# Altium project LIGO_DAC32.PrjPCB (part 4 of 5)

## Sheet LD32_Power.SchDoc: Power Top
size B; SheetNumber: 3; SheetTotal: 17; PageSetup: Record=PageOptions¦CenterHorizontal=True¦CenterVertical=True¦PrintScale=1.12¦XCorrection=1.00¦YCorrection=1.00¦PrintKind=0¦BorderSize=5000000¦LeftOffset=0¦BottomOffset=0¦Orientation=2¦PaperLength=1000¦PaperWidth=1000¦Scale=100¦PaperSource=7¦PrintQuality=-4¦MediaType=1¦DitherType=10¦PaperKind=Letter¦PrintScaleMode=1
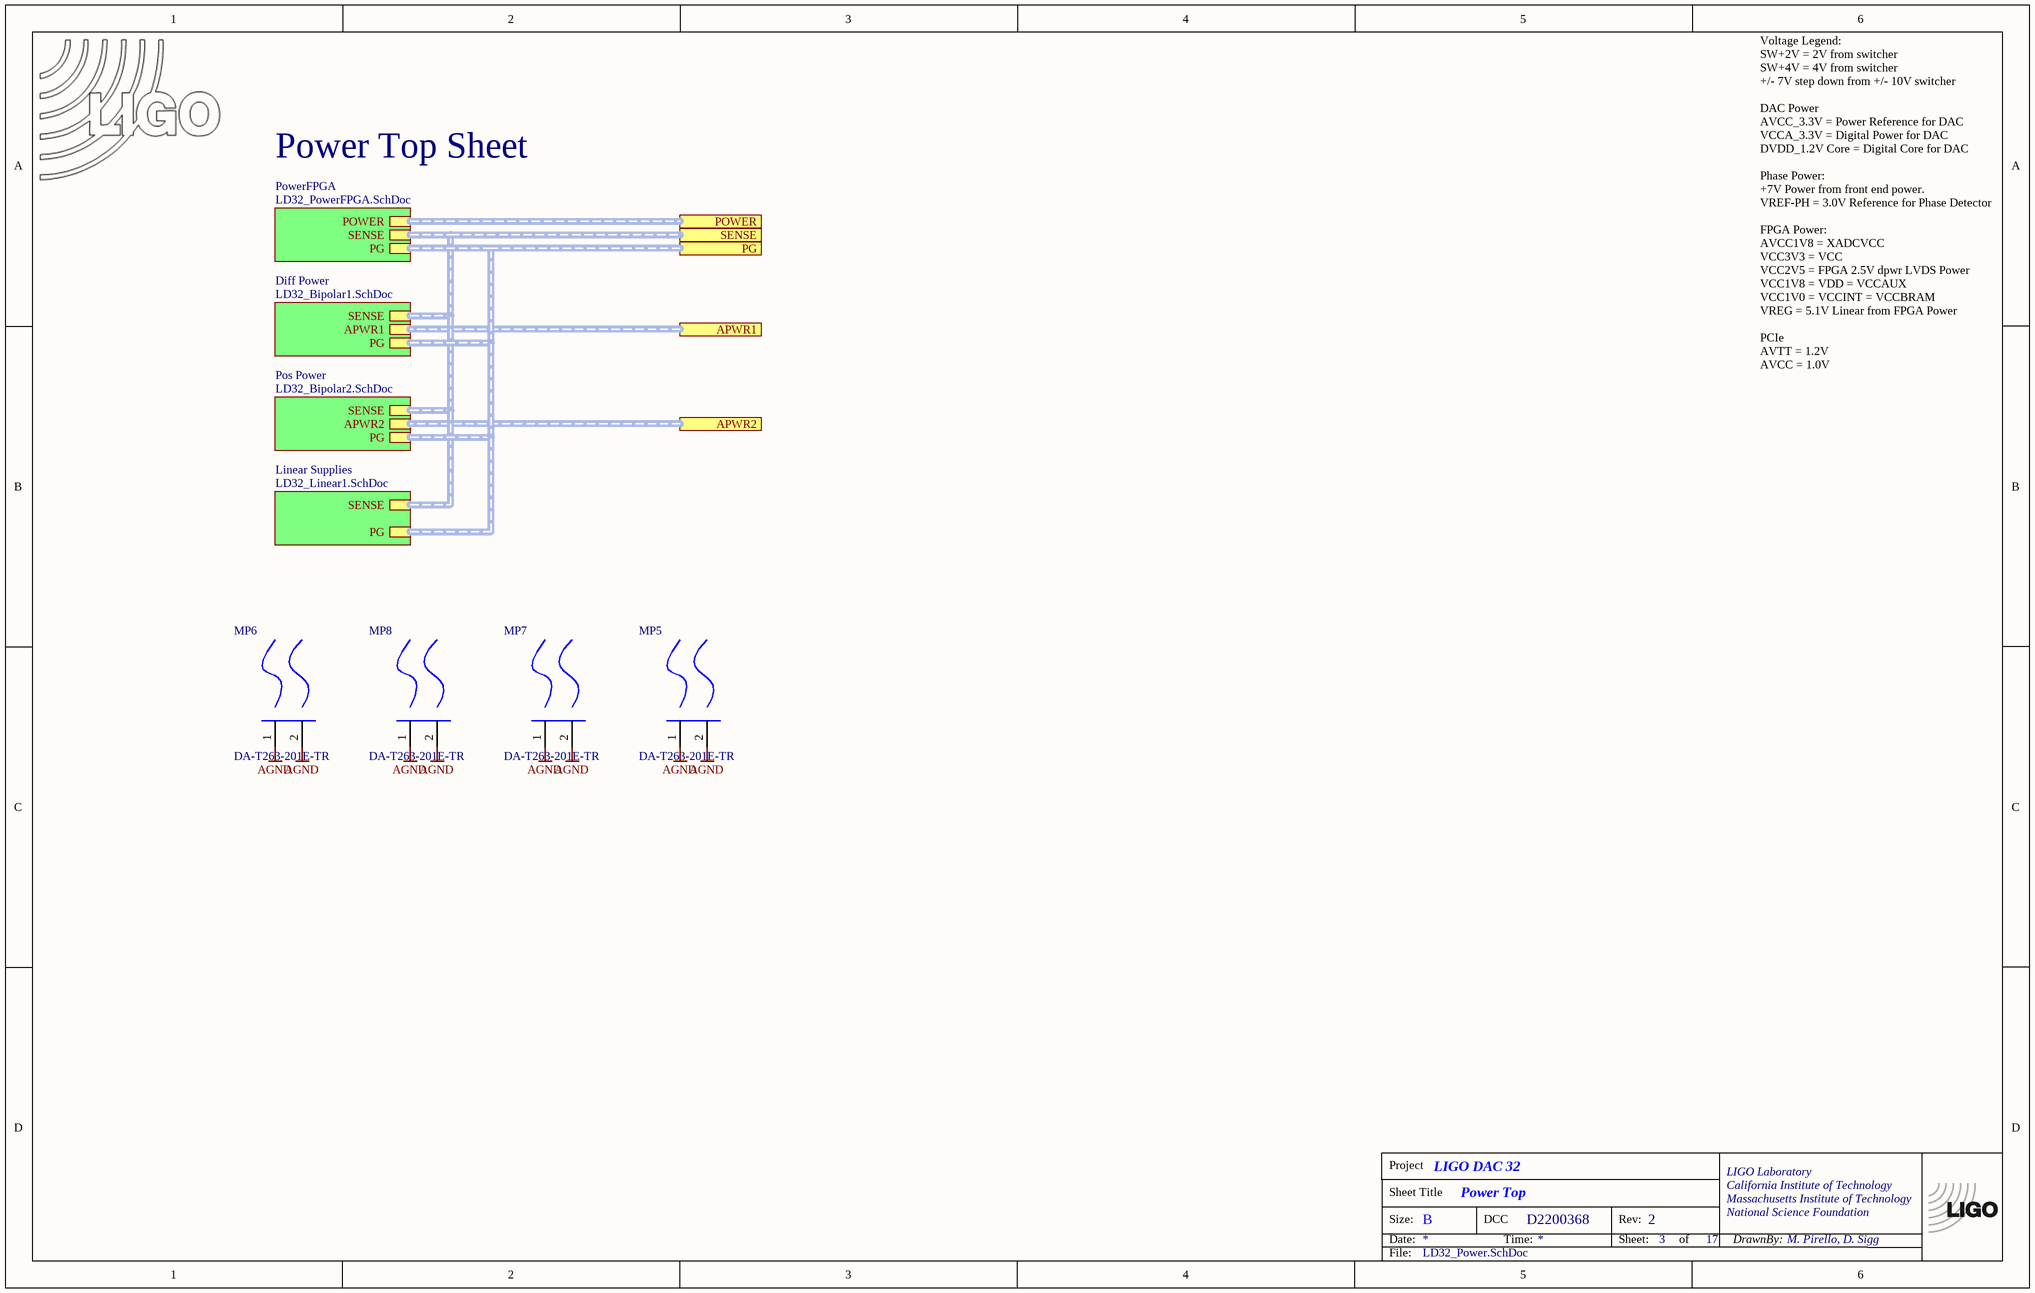
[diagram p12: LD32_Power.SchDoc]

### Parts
(Parts that share a designator on the sheet are numbered #1, #2 ... from top to bottom, then left to right.)
*?#9  TitleBlock  (value not drawn)  (graphical)
LOGO2#2  LIGO logo  [LIGO_LOGO]  (value not drawn)  (graphical)
MP5  DA-T263-201E-TR  [FP-DA-T263-201E-TR-MFG]
MP6  DA-T263-201E-TR  [FP-DA-T263-201E-TR-MFG]
MP7  DA-T263-201E-TR  [FP-DA-T263-201E-TR-MFG]
MP8  DA-T263-201E-TR  [FP-DA-T263-201E-TR-MFG]

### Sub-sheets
Diff Power = LD32_Bipolar1.SchDoc: APWR1 (harness APWR1), PG (harness APWR2), SENSE (harness SENSE)
Linear Supplies = LD32_Linear1.SchDoc: PG (harness APWR2), SENSE (harness SENSE)
Pos Power = LD32_Bipolar2.SchDoc: APWR2 (harness APWR2), PG (harness APWR2), SENSE (harness SENSE)
PowerFPGA = LD32_PowerFPGA.SchDoc: POWER (harness POWER), SENSE (harness SENSE), PG (harness APWR2)

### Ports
APWR1 (harness Inrush), APWR2 (harness Inrush), PG (harness Inrush), POWER (harness Inrush), SENSE (harness Inrush)

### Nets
AGND: MP5.1(MNT_1) MP5.2(MNT_2) MP6.1(MNT_1) MP6.2(MNT_2) MP7.1(MNT_1) MP7.2(MNT_2) MP8.1(MNT_1) MP8.2(MNT_2)

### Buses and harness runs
harness port APWR1 = sheet Diff Power/APWR1
harness port APWR2 = sheet Pos Power/APWR2
harness port PG = sheet Diff Power/PG = sheet Linear Supplies/PG = sheet Pos Power/PG = sheet PowerFPGA/PG
harness port POWER = sheet PowerFPGA/POWER
harness port SENSE = sheet Diff Power/SENSE = sheet Linear Supplies/SENSE = sheet Pos Power/SENSE = sheet PowerFPGA/SENSE

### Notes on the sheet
- Power Top Sheet
- Voltage Legend:
  SW+2V = 2V from switcher
  SW+4V = 4V from switcher
  +/- 7V step down from +/- 10V switcher
  DAC Power
  AVCC_3.3V = Power Reference for DAC
  VCCA_3.3V = Digital Power for DAC
  DVDD_1.2V Core = Digital Core for DAC
  Phase Power:
  +7V Power from front end power.
  VREF-PH = 3.0V Reference for Phase Detector
  FPGA Power:
  AVCC1V8 = XADCVCC
  VCC3V3 = VCC
  VCC2V5 = FPGA 2.5V dpwr LVDS Power
  VCC1V8 = VDD = VCCAUX
  VCC1V0 = VCCINT = VCCBRAM
  VREG = 5.1V Linear from FPGA Power
  PCIe
  AVTT = 1.2V
  AVCC = 1.0V

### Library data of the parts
LOGO2#2 = LIGO_logo
MP5-MP8 = CMP-33535-000006-1: HEATSINK FOR TO-263

## Sheet LD32_Bipolar1.SchDoc: Bipolar Analog Supply
size B; SheetNumber: 6; SheetTotal: 17
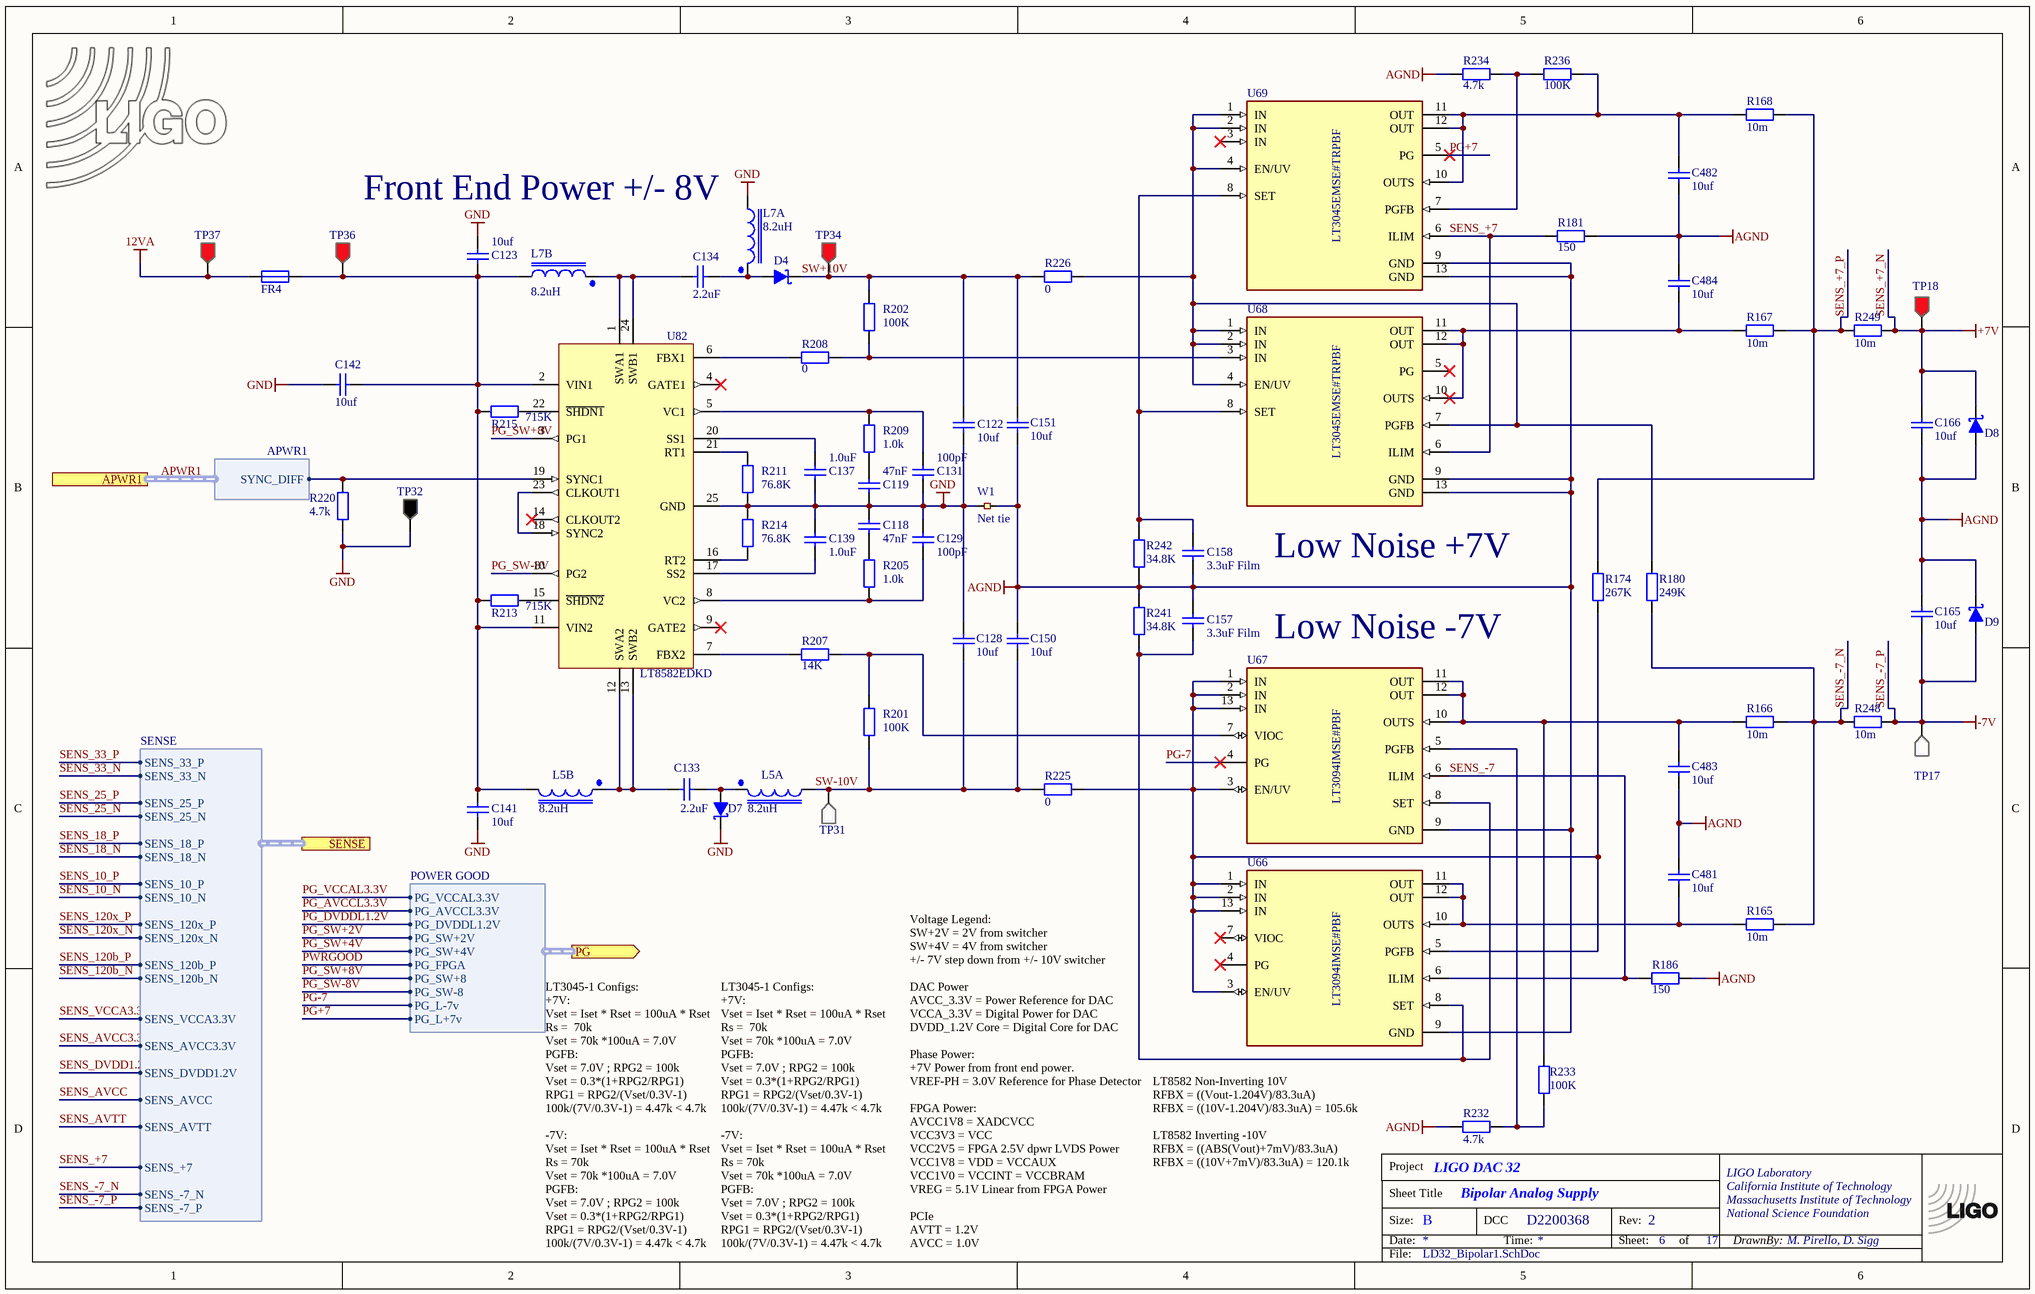
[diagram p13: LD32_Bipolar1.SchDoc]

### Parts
(Parts that share a designator on the sheet are numbered #1, #2 ... from top to bottom, then left to right.)
*?#10  TitleBlock  (value not drawn)  (graphical)
C118  47nF  [CC1005-0402]
C119  47nF  [CC1005-0402]
C122  10uF  [CC3225-1210]
C123  10uF  [CC3225-1210]
C128  10uF  [CC3225-1210]
C129  100pF  [CC1005-0402]
C131  100pF  [CC1005-0402]
C133  2.2uF  [CC3216-1206]
C134  2.2uF  [CC3216-1206]
C137  1.0uF  [CC1005-0402]
C139  1.0uF  [CC1005-0402]
C141  10uF  [CC3225-1210]
C142  10uF  [CC3225-1210]
C150  10uF  [CC3225-1210]
C151  10uF  [CC3225-1210]
C157  3.3uF Film  [CC3225-1210]
C158  3.3uF Film  [CC3225-1210]
C165  10uF  [CC3225-1210]
C166  10uF  [CC3225-1210]
C481  10uF  [CC3225-1210]
C482  10uF  [CC3225-1210]
C483  10uF  [CC3225-1210]
C484  10uF  [CC3225-1210]
D4  Schottky DO-PowerDI123  [DO-PowerDI123]  (value not drawn)
D7  Schottky DO-PowerDI123  [DO-PowerDI123]  (value not drawn)
D8  shottky diode  [DO-SMA]  (value not drawn)
D9  shottky diode  [DO-SMA]  (value not drawn)
FR4  BLM31PG121  [CC3216-1206]  (value not drawn)
L5  8.2uH  [MSD7342]  (parts A,B of 2)
L7  8.2uH  [MSD7342]  (parts A,B of 2)
LOGO?#4  LIGO logo  [LIGO_LOGO]  (value not drawn)  (graphical)
R165  10m  [CR1608-0603]
R166  10m  [CR1608-0603]
R167  10m  [CR1608-0603]
R168  10m  [CR1608-0603]
R174  267K  [CR1005-0402]
R180  249K  [CR1005-0402]
R181  150  [CR1005-0402]
R186  150  [CR1005-0402]
R201  100K  [CR1005-0402]
R202  100K  [CR1005-0402]
R205  1.0k  [CR1005-0402]
R207  14K  [CR1005-0402]
R208  0  [CR1005-0402]
R209  1.0k  [CR1005-0402]
R211  76.8K  [CR1005-0402]
R213  715K  [CR1005-0402]
R214  76.8K  [CR1005-0402]
R215  715K  [CR1005-0402]
R220  4.7k  [CR1005-0402]
R225  0  [CR1608-0603]
R226  0  [CR1608-0603]
R232  4.7k  [CR1005-0402]
R233  100K  [CR1005-0402]
R234  4.7k  [CR1005-0402]
R236  100K  [CR1005-0402]
R241  34.8K  [CR1005-0402]
R242  34.8K  [CR1005-0402]
R248  10m  [CR1608-0603]
R249  10m  [CR1608-0603]
TP17  Testpoint  [TP1-WHT]  (value not drawn)
TP18  Testpoint  [TP1-RED]  (value not drawn)
TP31  Testpoint  [TP1-WHT]  (value not drawn)
TP32  Testpoint  [TP1-BLK]  (value not drawn)
TP34  Testpoint  [TP1-RED]  (value not drawn)
TP36  Testpoint  [TP1-RED]  (value not drawn)
TP37  Testpoint  [TP1-RED]  (value not drawn)
U66  LT3094IMSE#PBF  [FP-MSE-12-05-08-1666-IPC_B]
U67  LT3094IMSE#PBF  [FP-MSE-12-05-08-1666-IPC_B]
U68  LT3045EMSE#TRPBF  [FP-MSE-12-05-08-1666-IPC_B]
U69  LT3045EMSE#TRPBF  [FP-MSE-12-05-08-1666-IPC_B]
U82  LT8582EDKD  [DFN-24_DKD]
W1  Net tie  [NETTIE1_SMDTOP]  (net tie, no BOM)

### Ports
APWR1 (harness APWR1), PG (out, harness Power good), SENSE (harness SENSE)

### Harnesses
APWR1: SYNC_DIFF
POWER GOOD: PG_VCCAL3.3V, PG_AVCCL3.3V, PG_DVDDL1.2V, PG_SW+2V, PG_SW+4V, PG_FPGA, PG_SW+8, PG_SW-8, PG_L-7v, PG_L+7v
SENSE: SENS_33_P, SENS_33_N, SENS_25_P, SENS_25_N, SENS_18_P, SENS_18_N, SENS_10_P, SENS_10_N, SENS_120x_P, SENS_120x_N, SENS_120b_P, SENS_120b_N, SENS_VCCA3.3V, SENS_AVCC3.3V, SENS_DVDD1.2V, SENS_+7, SENS_-7_P, SENS_AVTT, SENS_AVCC, SENS_-7_N

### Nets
12VA: FR4.1 TP37.1
+7V: C166.2 D8.2(K) R249.1 TP18.1  [also labelled SENS_+7_N]
-7V: C165.1 D9.1(A) R248.1 TP17.1 ; port SENSE.SENS_-7_P  [also labelled SENS_-7_P]
AGND: C150.1 C151.2 C157.2 C158.1 C165.2 C166.1 C481.2 C482.1 C483.1 C484.2 D8.1(A) D9.2(K) R181.1 R186.1 R232.2 R234.2 R241.2 R242.1 U66.9(GND) U67.9(GND) U68.9(GND) U68.13(GND) U69.9(GND) U69.13(GND) W1.2
GND: C118.2 C119.1 C122.1 C123.2 C128.2 C129.2 C131.1 C137.1 C139.2 C141.1 C142.2 D7.2(K) L7.3 R211.1 R214.2 R220.2 TP32.1 U82.25(GND) W1.1
APWR1.SYNC_DIFF: R220.1 U82.19(SYNC1) ; port APWR1.SYNC_DIFF
PG+7: U69.5(PG) ; port PG.PG_L+7v  [project net PG.PG_L+7v]
PG-7: U67.4(PG) ; port PG.PG_L-7v  [project net PG.PG_L-7v]
PG_SW+8V: U82.3(PG1) ; port PG.PG_SW+8  [project net PG.PG_SW+8]
PG_SW-8V: U82.10(PG2) ; port PG.PG_SW-8  [project net PG.PG_SW-8]
SENS_+7: R181.2 U68.6(ILIM) U69.6(ILIM) ; port SENSE.SENS_+7  [project net SENSE.SENS_+7]
SENS_+7_P: R167.1 R168.1 R174.2 R249.2
SENS_-7: R186.2 U66.6(ILIM) U67.6(ILIM)
SENS_-7_N: R165.1 R166.1 R180.1 R248.2 ; port SENSE.SENS_-7_N  [project net SENSE.SENS_-7_N]
SW+10V: C122.2 C151.1 D4.2(K) R202.2 R226.2 TP34.1
SW-10V: C128.1 C150.2 L5.3 R201.1 R225.2 TP31.1
NetC118_1: C118.1 R205.2
NetC119_2: C119.2 R209.1
NetC123_1: C123.1 C141.2 C142.1 FR4.2 L5.4 L7.4 R213.2 R215.2 TP36.1 U82.2(VIN1) U82.11(VIN2)
NetC129_1: C129.1 R205.1 U82.8(VC2)
NetC131_2: C131.2 R209.2 U82.5(VC1)
NetC133_1: C133.1 D7.1(A) L5.1
NetC133_2: C133.2 L5.2 U82.12(SWA2) U82.13(SWB2)
NetC134_1: C134.1 D4.1(A) L7.1
NetC134_2: C134.2 L7.2 U82.1(SWA1) U82.24(SWB1)
NetC137_2: C137.2 U82.20(SS1)
NetC139_1: C139.1 U82.17(SS2)
NetC157_1: C157.1 R241.1 U66.8(SET) U67.8(SET)
NetC158_2: C158.2 R242.2 U68.8(SET) U69.8(SET)
NetC481_1: C481.1 R165.2 U66.10(OUTS) U66.11(OUT) U66.12(OUT)
NetC482_2: C482.2 R168.2 R236.1 U69.10(OUTS) U69.11(OUT) U69.12(OUT)
NetC483_2: C483.2 R166.2 R233.1 U67.10(OUTS) U67.11(OUT) U67.12(OUT)
NetC484_1: C484.1 R167.2 U68.10(OUTS) U68.11(OUT) U68.12(OUT)
NetR174_1: R174.1 R225.1 U66.1(IN) U66.2(IN) U66.3(EN/UV) U66.5(PGFB) U66.13(IN) U67.1(IN) U67.2(IN) U67.3(EN/UV) U67.13(IN)
NetR180_2: R180.2 R226.1 U68.1(IN) U68.2(IN) U68.4(EN/UV) U68.7(PGFB) U69.1(IN) U69.2(IN) U69.4(EN/UV)
NetR201_2: R201.2 R207.1 U67.7(VIOC)
NetR202_1: R202.1 R208.1 U68.3(IN)
NetR207_2: R207.2 U82.7(FBX2)
NetR208_2: R208.2 U82.6(FBX1)
NetR211_2: R211.2 U82.21(RT1)
NetR213_1: R213.1 U82.15(~{SHDN2})
NetR214_1: R214.1 U82.16(RT2)
NetR215_1: R215.1 U82.22(~{SHDN1})
NetR232_1: R232.1 R233.2 U67.5(PGFB)
NetR234_1: R234.1 R236.2 U69.7(PGFB)
NetU82_18: U82.18(SYNC2) U82.23(CLKOUT1)

Not connected (* = marked no-connect by the designer): U66 4(PG)* 7(VIOC)*; U68 5(PG)*; U69 3(IN)*; U82 4(GATE1)* 9(GATE2)* 14(CLKOUT2)*

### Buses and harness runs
harness APWR1 = port APWR1

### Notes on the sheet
- (near L7) Front End Power +/- 8V
- (near U68) Low Noise +7V
- (near U67) Low Noise -7V
- Voltage Legend:
  SW+2V = 2V from switcher
  SW+4V = 4V from switcher
  +/- 7V step down from +/- 10V switcher
  DAC Power
  AVCC_3.3V = Power Reference for DAC
  VCCA_3.3V = Digital Power for DAC
  DVDD_1.2V Core = Digital Core for DAC
  Phase Power:
  +7V Power from front end power.
  VREF-PH = 3.0V Reference for Phase Detector
  FPGA Power:
  AVCC1V8 = XADCVCC
  VCC3V3 = VCC
  VCC2V5 = FPGA 2.5V dpwr LVDS Power
  VCC1V8 = VDD = VCCAUX
  VCC1V0 = VCCINT = VCCBRAM
  VREG = 5.1V Linear from FPGA Power
  PCIe
  AVTT = 1.2V
  AVCC = 1.0V
- LT8582 Non-Inverting 10V
  RFBX = ((Vout-1.204V)/83.3uA)
  RFBX = ((10V-1.204V)/83.3uA) = 105.6k
  LT8582 Inverting -10V
  RFBX = ((ABS(Vout)+7mV)/83.3uA)
  RFBX = ((10V+7mV)/83.3uA) = 120.1k
- LT3045-1 Configs:
  +7V:
  Vset = Iset * Rset = 100uA * Rset
  Rs =  70k
  Vset = 70k *100uA = 7.0V
  PGFB:
  Vset = 7.0V ; RPG2 = 100k
  Vset = 0.3*(1+RPG2/RPG1)
  RPG1 = RPG2/(Vset/0.3V-1)
  100k/(7V/0.3V-1) = 4.47k < 4.7k
  -7V:
  Vset = Iset * Rset = 100uA * Rset
  Rs = 70k
  Vset = 70k *100uA = 7.0V
  PGFB:
  Vset = 7.0V ; RPG2 = 100k
  Vset = 0.3*(1+RPG2/RPG1)
  RPG1 = RPG2/(Vset/0.3V-1)
  100k/(7V/0.3V-1) = 4.47k < 4.7k
  RPG2 = (7.0/0.3-1)*50k = 1116k > 1M

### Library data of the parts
C118 C119 = ChipCap: C0402 47nF; Part Number: 0402B473J250CT
C122 C123 C128 C141 C142 C150 C151 C165 C166 C481-C484 = ChipCap: C1210 10uF; Part Number: CL32B106KBJNNNE
C129 C131 = ChipCap: C0402 0.1nF; Part Number: 04025A101JAT2A
C133 C134 = ChipCap: C1206 2.2u; Part Number: C1206C225J5RECAUTO
C137 C139 = ChipCap: C0402 1.0uF; Part Number: C0402C105K4PACTU
C157 C158 = ChipCap: C1210 3.3uF Film; Part Number: 16MU335MB33225
D4 D7 = DIODE_SHOTTKY: Part Number: DFLS230-7
D8 D9 = DIODE_SHOTTKY: Single shottky diode; Part Number: CDBA340L-G
FR4 = BLM31PG121SN1: ferrite bead, 120Ohm at 100MHz, 1206; Part Number: BLM31PG121SN1L
L5 L7 = MSD7342: Shielded Coupled Inductors, MSD7342 series 8.2uH; Part Number: MSD7342-822MLC
LOGO?#4 = LIGO_logo
R165-R168 R248 R249 = ChipRes1: R0603 10m; Part Number: CFN0603AFZ-R010ELF
R174 = ChipRes1: R0402 267k; Part Number: ERJ-2RKF2673X
R180 = ChipRes1: R0402 249k; Part Number: RC0402FR-07249KL
R181 R186 = ChipRes1: R0402 150; Part Number: ERA-2AEB151X
R201 R202 R233 R236 = ChipRes1: R0402 100k; Part Number: ERA-2AEB104X
R205 R209 = ChipRes1: R0402 1.0k; Part Number: ERA-2AEB102X
R207 = ChipRes1: R0402 14k; Part Number: ERA-2AEB1402X
R208 = ChipRes1: R0402 0; Part Number: AC0402FR-070RL
R211 R214 = ChipRes1: R0402 76.8k; Part Number: RT0402DRE0776K8L
R213 R215 = ChipRes1: R0402 715k; Part Number: ERA-2AEB7150X
R220 R232 R234 = ChipRes1: R0402 4.7k; Part Number: ERA-2AED472X
R225 R226 = ChipRes1: R0603 0; Part Number: RMCF0603ZT0R00
R241 R242 = ChipRes1: R0402 34.8k; Part Number: RT0402DRD0734K8L
TP17 TP31 = TP_NEGATIVE: Testpoint, white; Part Number: Keystone / 5002
TP18 TP34 TP36 TP37 = TP_POSITIVE: Testpoint, red; Part Number: Keystone / 5000
TP32 = TP_GND: Testpoint, black; Part Number: Keystone / 5001
U66 U67 = CMP-09138-000085-1: IC REG LIN NEG ADJ 500MA 12MSOP
U68 U69 = CMP-09138-000053-1: IC REG LINEAR 0V 500MA 12MSOP; Part Number: LT3045EMSE-1#PBF
U82 = LT8582: Dual 3A Boost/Inverting/SEPIC DC/DC Converter with Fault Protection; Part Number: LT8582EDKD#PBF
W1 = NetTie1_small: Tie two nets together; Part Number: NL

## Sheet LD32_Linear1.SchDoc: Linear Supplies
size B; SheetNumber: 4; SheetTotal: 17
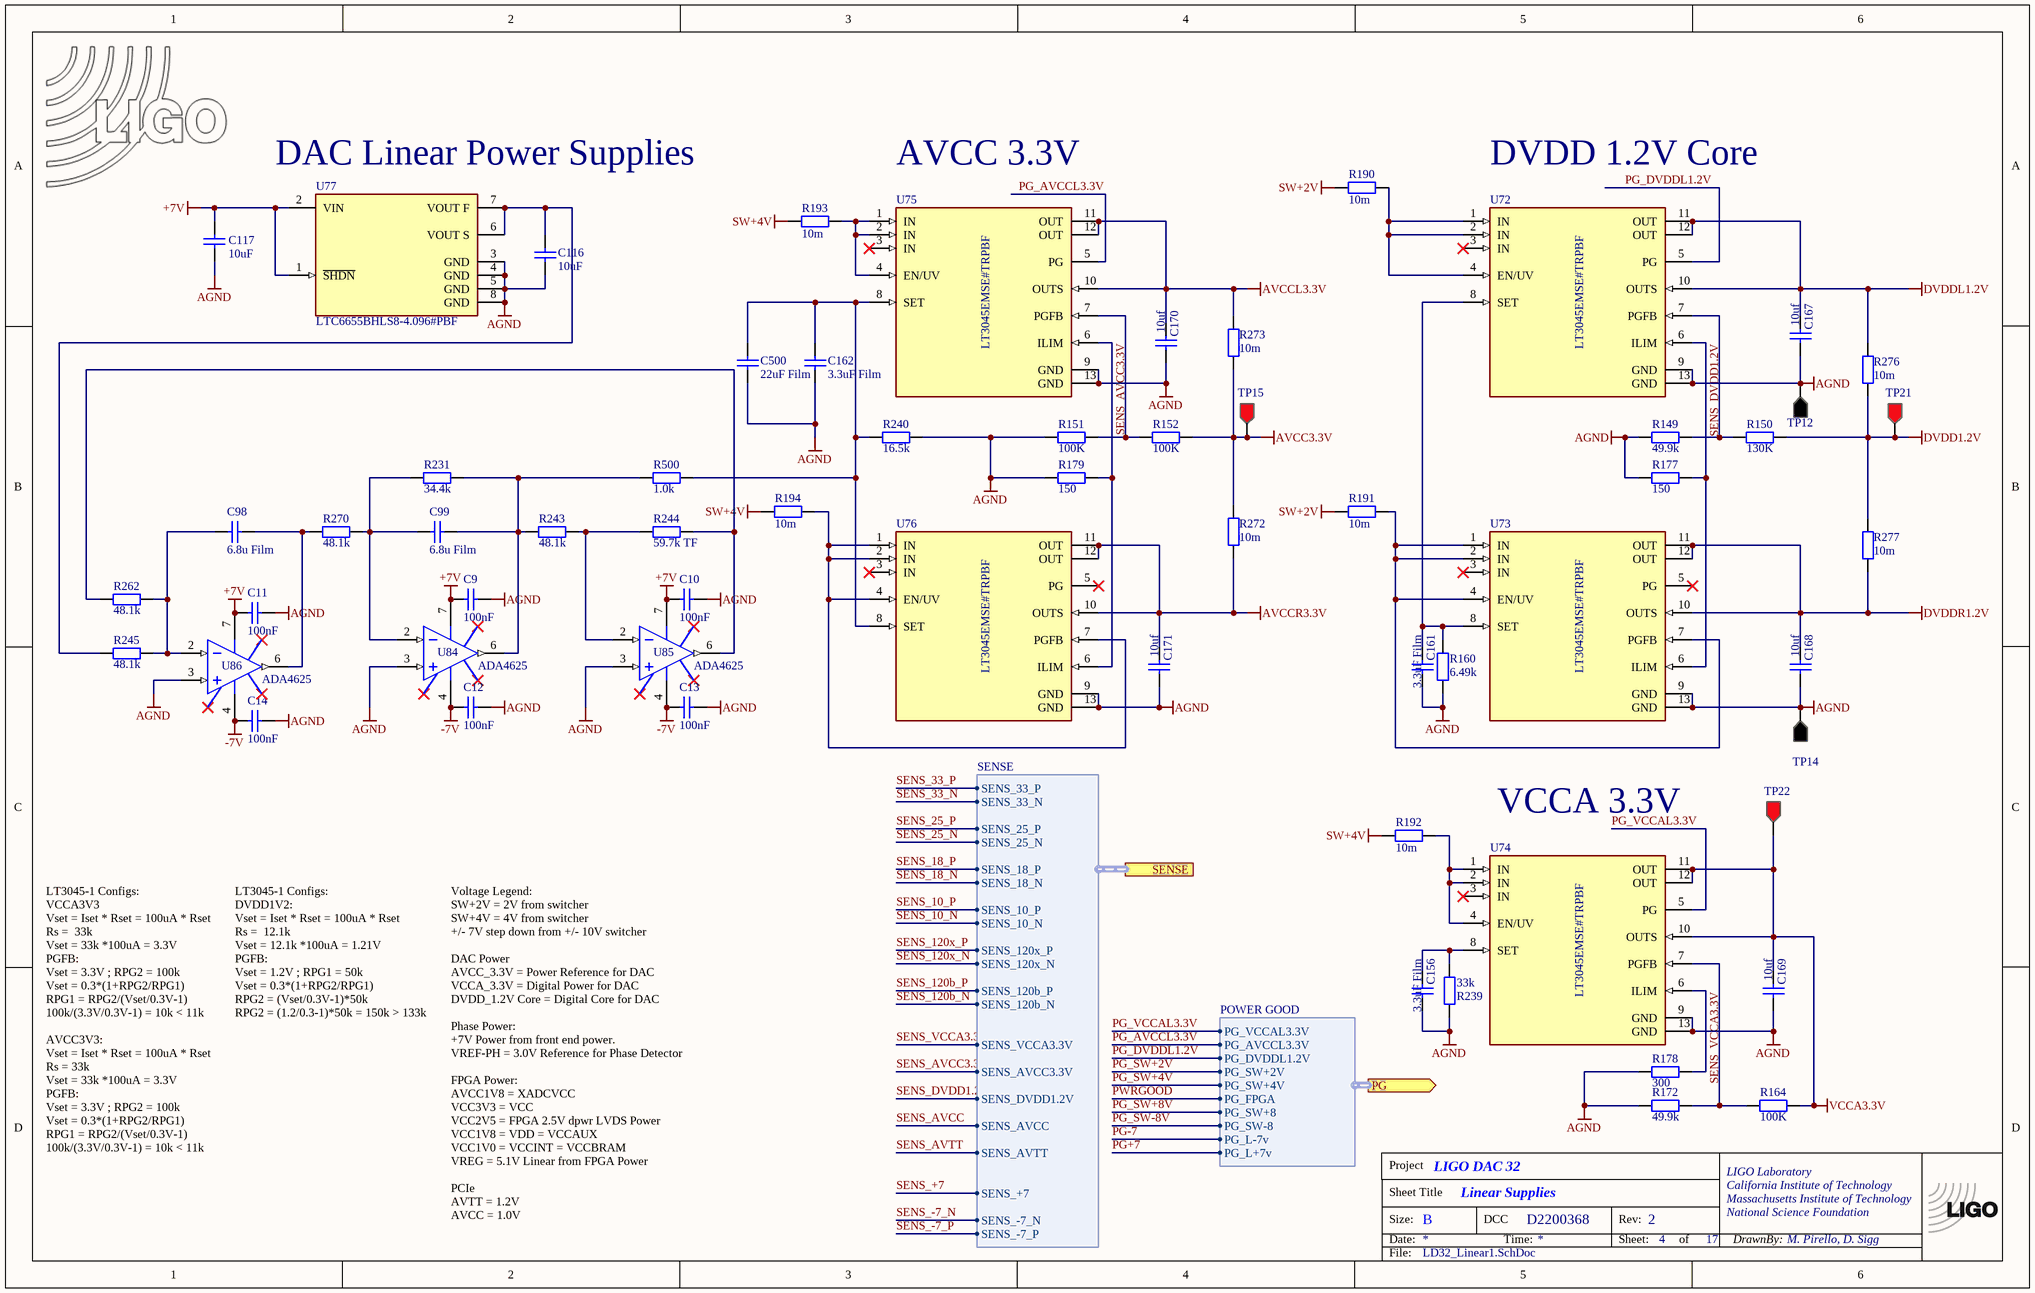
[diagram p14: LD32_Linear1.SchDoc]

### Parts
(Parts that share a designator on the sheet are numbered #1, #2 ... from top to bottom, then left to right.)
*?#11  TitleBlock  (value not drawn)  (graphical)
C9  100nF  [CC0603-0201]
C10  100nF  [CC0603-0201]
C11  100nF  [CC0603-0201]
C12  100nF  [CC0603-0201]
C13  100nF  [CC0603-0201]
C14  100nF  [CC0603-0201]
C98  6.8u Film  [MKS2B046801M00]
C99  6.8u Film  [MKS2B046801M00]
C116  10uF  [CC2013-0805]
C117  10uF  [CC2013-0805]
C156  3.3uF Film  [CC3225-1210]
C161  3.3uF Film  [CC3225-1210]
C162  3.3uF Film  [CC3225-1210]
C167  10uF  [CC3225-1210]
C168  10uF  [CC3225-1210]
C169  10uF  [CC3225-1210]
C170  10uF  [CC3225-1210]
C171  10uF  [CC3225-1210]
C500  value 22uF Film  [CC5650-2220]  (hidden comment: 22uF)
LOGO?#5  LIGO logo  [LIGO_LOGO]  (value not drawn)  (graphical)
R149  49.9k  [CR1005-0402]
R150  130K  [CR1005-0402]
R151  100K  [CR1005-0402]
R152  100K  [CR1005-0402]
R160  6.49k  [CR1608-0603]
R164  100K  [CR1005-0402]
R172  49.9k  [CR1005-0402]
R177  150  [CR1005-0402]
R178  300  [CR1005-0402]
R179  150  [CR1005-0402]
R190  10m  [CR1608-0603]
R191  10m  [CR1608-0603]
R192  10m  [CR1608-0603]
R193  10m  [CR1608-0603]
R194  10m  [CR1608-0603]
R231  34.4k  [CR1608-0603]
R239  33k  [CR1005-0402]
R240  16.5k  [CR1005-0402]
R243  48.1k  [CR1608-0603]
R244  59.7k TF  [CR1608-0603]
R245  48.1k  [CR1608-0603]
R262  48.1k  [CR1608-0603]
R270  48.1k  [CR1608-0603]
R272  10m  [CR1608-0603]
R273  10m  [CR1608-0603]
R276  10m  [CR1608-0603]
R277  10m  [CR1608-0603]
R500  1.0k  [CR1005-0402]
TP12  Testpoint  [TP1-BLK]  (value not drawn)
TP14  Testpoint  [TP1-BLK]  (value not drawn)
TP15  Testpoint  [TP1-RED]  (value not drawn)
TP21  Testpoint  [TP1-RED]  (value not drawn)
TP22  Testpoint  [TP1-RED]  (value not drawn)
U72  LT3045EMSE#TRPBF  [FP-MSE-12-05-08-1666-IPC_B]
U73  LT3045EMSE#TRPBF  [FP-MSE-12-05-08-1666-IPC_B]
U74  LT3045EMSE#TRPBF  [FP-MSE-12-05-08-1666-IPC_B]
U75  LT3045EMSE#TRPBF  [FP-MSE-12-05-08-1666-IPC_B]
U76  LT3045EMSE#TRPBF  [FP-MSE-12-05-08-1666-IPC_B]
U77  LTC6655BHLS8-4.096#PBF  [FP-LS8-8-05-08-1852-MFG]
U84  ADA4625  [SO-G8]
U85  ADA4625  [SO-G8]
U86  ADA4625  [SO-G8]

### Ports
PG (out, harness Power good), SENSE (harness SENSE)

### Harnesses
POWER GOOD: PG_VCCAL3.3V, PG_AVCCL3.3V, PG_DVDDL1.2V, PG_SW+2V, PG_SW+4V, PG_FPGA, PG_SW+8, PG_SW-8, PG_L-7v, PG_L+7v
SENSE: SENS_33_P, SENS_33_N, SENS_25_P, SENS_25_N, SENS_18_P, SENS_18_N, SENS_10_P, SENS_10_N, SENS_120x_P, SENS_120x_N, SENS_120b_P, SENS_120b_N, SENS_VCCA3.3V, SENS_AVCC3.3V, SENS_DVDD1.2V, SENS_+7, SENS_-7_P, SENS_AVTT, SENS_AVCC, SENS_-7_N

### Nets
+7V: C9.1 C10.1 C11.1 C117.2 U77.1(~{SHDN}) U77.2(VIN) U84.7(V+) U85.7(V+) U86.7(V+)
-7V: C12.1 C13.1 C14.1 U84.4(V-) U85.4(V-) U86.4(V-) ; port SENSE.SENS_-7_P  [also labelled SENS_-7_P]
AGND: C9.2 C10.2 C11.2 C12.2 C13.2 C14.2 C116.2 C117.1 C156.1 C161.1 C162.1 C167.1 C168.1 C169.1 C170.1 C171.1 C500.1 R149.2 R151.2 R160.2 R172.2 R177.2 R178.2 R179.2 R239.1 R240.1 TP12.1 TP14.1 U72.9(GND) U72.13(GND) U73.9(GND) U73.13(GND) U74.9(GND) U74.13(GND) U75.9(GND) U75.13(GND) U76.9(GND) U76.13(GND) U77.3(GND) U77.4(GND) U77.5(GND) U77.8(GND) U84.3(IN+) U85.3(IN+) U86.3(IN+)
AVCC3.3V: R152.1 R272.1 R273.2 TP15.1
AVCCL3.3V: C170.2 R273.1 U75.10(OUTS) U75.11(OUT) U75.12(OUT)
AVCCR3.3V: C171.2 R272.2 U76.10(OUTS) U76.11(OUT) U76.12(OUT)
DVDD1.2V: R150.1 R276.2 R277.1 TP21.1
DVDDL1.2V: C167.2 R276.1 U72.10(OUTS) U72.11(OUT) U72.12(OUT)
DVDDR1.2V: C168.2 R277.2 U73.10(OUTS) U73.11(OUT) U73.12(OUT)
SW+2V: R190.2 R191.2
SW+4V: R192.2 R193.2 R194.2
VCCA3.3V: C169.2 R164.1 TP22.1 U74.10(OUTS) U74.11(OUT) U74.12(OUT)
PG_AVCCL3.3V: U75.5(PG) ; port PG.PG_AVCCL3.3V  [project net PG.PG_AVCCL3.3V]
PG_DVDDL1.2V: U72.5(PG) ; port PG.PG_DVDDL1.2V  [project net PG.PG_DVDDL1.2V]
PG_VCCAL3.3V: U74.5(PG) ; port PG.PG_VCCAL3.3V  [project net PG.PG_VCCAL3.3V]
SENS_AVCC3.3V: R179.1 U75.6(ILIM) U76.6(ILIM) ; port SENSE.SENS_AVCC3.3V  [project net SENSE.SENS_AVCC3.3V]
SENS_DVDD1.2V: R177.1 U72.6(ILIM) U73.6(ILIM) ; port SENSE.SENS_DVDD1.2V  [project net SENSE.SENS_DVDD1.2V]
SENS_VCCA3.3V: R178.1 U74.6(ILIM) ; port SENSE.SENS_VCCA3.3V  [project net SENSE.SENS_VCCA3.3V]
NetC98_1: C98.1 R245.1 R262.1 U86.2(IN-)
NetC98_2: C98.2 R270.2 U86.6(OUT)
NetC99_1: C99.1 R231.2 R270.1 U84.2(IN-)
NetC99_2: C99.2 R231.1 R243.2 R500.2 U84.6(OUT)
NetC116_1: C116.1 R245.2 U77.6(VOUT_S) U77.7(VOUT_F)
NetC156_2: C156.2 R239.2 U74.8(SET)
NetC161_2: C161.2 R160.1 U72.8(SET) U73.8(SET)
NetC162_2: C162.2 C500.2 R240.2 R500.1 U75.8(SET) U76.8(SET)
NetR149_1: R149.1 R150.2 U72.7(PGFB)
NetR151_1: R151.1 R152.2 U75.7(PGFB)
NetR164_2: R164.2 R172.1 U74.7(PGFB)
NetR190_1: R190.1 U72.1(IN) U72.2(IN) U72.4(EN/UV)
NetR191_1: R191.1 U73.1(IN) U73.2(IN) U73.4(EN/UV) U73.7(PGFB)
NetR192_1: R192.1 U74.1(IN) U74.2(IN) U74.4(EN/UV)
NetR193_1: R193.1 U75.1(IN) U75.2(IN) U75.4(EN/UV)
NetR194_1: R194.1 U76.1(IN) U76.2(IN) U76.4(EN/UV) U76.7(PGFB)
NetR243_1: R243.1 R244.2 U85.2(IN-)
NetR244_1: R244.1 R262.2 U85.6(OUT)

Not connected (* = marked no-connect by the designer): U72 3(IN)*; U73 3(IN)* 5(PG)*; U74 3(IN)*; U75 3(IN)*; U76 3(IN)* 5(PG)*; U84 1(TRIM) 5(NC) 8(TRIM); U85 1(TRIM) 5(NC) 8(TRIM); U86 1(TRIM) 5(NC) 8(TRIM)

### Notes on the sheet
- (near U77) DAC Linear Power Supplies
- (near U75) AVCC 3.3V
- (near U72) DVDD 1.2V Core
- VCCA 3.3V
- LT3045-1 Configs:
  DVDD1V2:
  Vset = Iset * Rset = 100uA * Rset
  Rs =  12.1k
  Vset = 12.1k *100uA = 1.21V
  PGFB:
  Vset = 1.2V ; RPG1 = 50k
  Vset = 0.3*(1+RPG2/RPG1)
  RPG2 = (Vset/0.3V-1)*50k
  RPG2 = (1.2/0.3-1)*50k = 150k > 133k
- LT3045-1 Configs:
  VCCA3V3
  Vset = Iset * Rset = 100uA * Rset
  Rs =  33k
  Vset = 33k *100uA = 3.3V
  PGFB:
  Vset = 3.3V ; RPG2 = 100k
  Vset = 0.3*(1+RPG2/RPG1)
  RPG1 = RPG2/(Vset/0.3V-1)
  100k/(3.3V/0.3V-1) = 10k < 11k
  AVCC3V3:
  Vset = Iset * Rset = 100uA * Rset
  Rs = 33k
  Vset = 33k *100uA = 3.3V
  PGFB:
  Vset = 3.3V ; RPG2 = 100k
  Vset = 0.3*(1+RPG2/RPG1)
  RPG1 = RPG2/(Vset/0.3V-1)
  100k/(3.3V/0.3V-1) = 10k < 11k
- Voltage Legend:
  SW+2V = 2V from switcher
  SW+4V = 4V from switcher
  +/- 7V step down from +/- 10V switcher
  DAC Power
  AVCC_3.3V = Power Reference for DAC
  VCCA_3.3V = Digital Power for DAC
  DVDD_1.2V Core = Digital Core for DAC
  Phase Power:
  +7V Power from front end power.
  VREF-PH = 3.0V Reference for Phase Detector
  FPGA Power:
  AVCC1V8 = XADCVCC
  VCC3V3 = VCC
  VCC2V5 = FPGA 2.5V dpwr LVDS Power
  VCC1V8 = VDD = VCCAUX
  VCC1V0 = VCCINT = VCCBRAM
  VREG = 5.1V Linear from FPGA Power
  PCIe
  AVTT = 1.2V
  AVCC = 1.0V

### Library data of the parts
C9-C14 = ChipCap: C0201 0.1uF; Part Number: 490-GRM033Z71C104KE14DCT-ND
C98 C99 = CapFilmRadial: Film Capacitor 6.8u Radial
C116 C117 = ChipCap: C0805 10uF; Part Number: CL21A106KAYNNNG
C156 C161 C162 = ChipCap: as C157 on sheet LD32_Bipolar1
C167-C171 = ChipCap: C1210 10uF; Part Number: CL32B106KBJNNNE
C500 = ChipCap: C2220 22uF; Part Number: 16MU226MD35750
LOGO?#5 = LIGO_logo
R149 R172 = ChipRes1: R0402 49.9k; Part Number: RR0510P-4992-D
R150 = ChipRes1: R0402 130k; Part Number: RP73PF1E130KBTD
R151 R152 R164 = ChipRes1: R0402 100k; Part Number: ERA-2AEB104X
R160 = ChipRes1: R0603 6.49k; Part Number: ERA-3AEB6491V
R177 R179 = ChipRes1: R0402 150; Part Number: ERA-2AEB151X
R178 = ChipRes1: R0402 300; Part Number: RR05P300DCT-ND
R190-R194 R272 R273 R276 R277 = ChipRes1: as R165 on sheet LD32_Bipolar1
R231 = ChipRes1: R0603 34.4k; Part Number: RN73H1JTTD3442F100
R239 = ChipRes1: R0402 33k; Part Number: RT0402FRE0733KL
R240 = ChipRes1: R0402 16.5k; Part Number: RT0402BRD0716K5L
R243 R245 R262 R270 = ChipRes1: R0603 48.1k; Part Number: RT0603BRD0748K1L
R244 = ChipRes1: R0603 59.7k TF; Part Number: RT0603BRD0759K7L
R500 = ChipRes1: R0402 1.0k; Part Number: ERA-2AEB102X
TP12 TP14 = TP_GND: as TP32 on sheet LD32_Bipolar1
TP15 TP21 TP22 = TP_POSITIVE: as TP18 on sheet LD32_Bipolar1
U72-U76 = CMP-09138-000053-1: as U68 on sheet LD32_Bipolar1
U77 = CMP-09137-000088-1: IC VREF SERIES 0.025% 8CLCC
U84-U86 = OpAmp: Op Amp; Part Number: ADA4625-1ARDZ-R7

## Sheet LD32_Bipolar2.SchDoc: Dual Analog Supply
size B; SheetNumber: 7; SheetTotal: 17
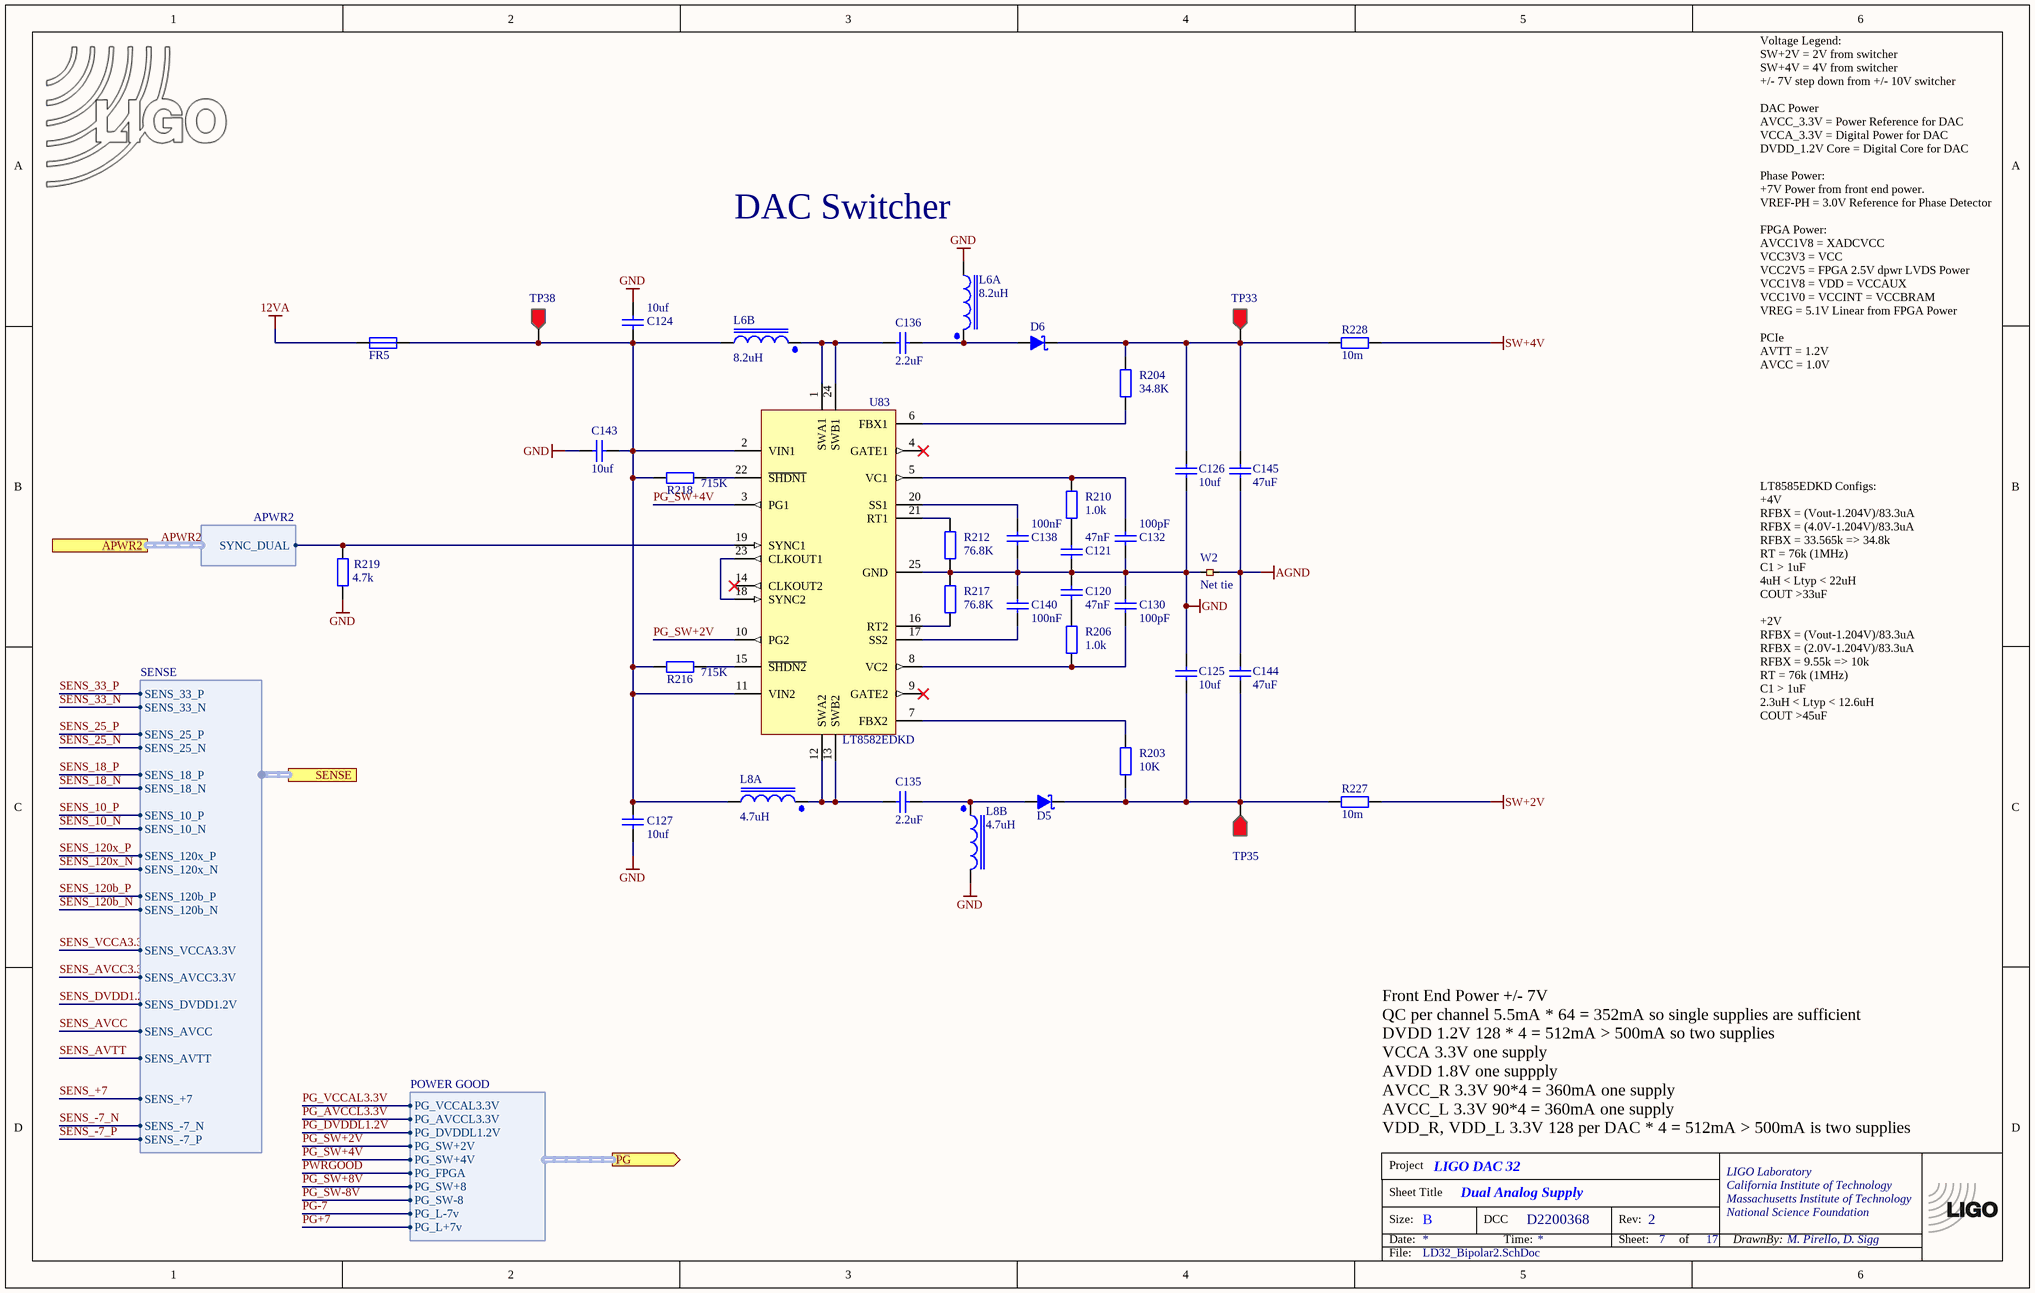
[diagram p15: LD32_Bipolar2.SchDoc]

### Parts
(Parts that share a designator on the sheet are numbered #1, #2 ... from top to bottom, then left to right.)
*?#12  TitleBlock  (value not drawn)  (graphical)
C120  47nF  [CC1005-0402]
C121  47nF  [CC1005-0402]
C124  10uF  [CC3225-1210]
C125  10uF  [CC3225-1210]
C126  10uF  [CC3225-1210]
C127  10uF  [CC3225-1210]
C130  100pF  [CC1005-0402]
C132  100pF  [CC1005-0402]
C135  2.2uF  [CC3216-1206]
C136  2.2uF  [CC3216-1206]
C138  100nF  [CC1005-0402]
C140  100nF  [CC1005-0402]
C143  10uF  [CC3225-1210]
C144  47uF  [CC5650-2220]
C145  47uF  [CC5650-2220]
D5  Schottky DO-PowerDI123  [DO-PowerDI123]  (value not drawn)
D6  Schottky DO-PowerDI123  [DO-PowerDI123]  (value not drawn)
FR5  BLM31PG121  [CC3216-1206]  (value not drawn)
L6  8.2uH  [MSD7342]  (parts A,B of 2)
L8  4.7uH  [MSD7342]  (parts A,B of 2)
LOGO?#6  LIGO logo  [LIGO_LOGO]  (value not drawn)  (graphical)
R203  10K  [CR1005-0402]
R204  34.8K  [CR1005-0402]
R206  1.0k  [CR1005-0402]
R210  1.0k  [CR1005-0402]
R212  76.8K  [CR1005-0402]
R216  715K  [CR1005-0402]
R217  76.8K  [CR1005-0402]
R218  715K  [CR1005-0402]
R219  4.7k  [CR1005-0402]
R227  10m  [CR1608-0603]
R228  10m  [CR1608-0603]
TP33  Testpoint  [TP1-RED]  (value not drawn)
TP35  Testpoint  [TP1-RED]  (value not drawn)
TP38  Testpoint  [TP1-RED]  (value not drawn)
U83  LT8582EDKD  [DFN-24_DKD]
W2  Net tie  [NETTIE1_SMDTOP]  (net tie, no BOM)

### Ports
APWR2 (harness APWR2), PG (out, harness Power good), SENSE (harness SENSE)

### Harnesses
APWR2: SYNC_DUAL
POWER GOOD: PG_VCCAL3.3V, PG_AVCCL3.3V, PG_DVDDL1.2V, PG_SW+2V, PG_SW+4V, PG_FPGA, PG_SW+8, PG_SW-8, PG_L-7v, PG_L+7v
SENSE: SENS_33_P, SENS_33_N, SENS_25_P, SENS_25_N, SENS_18_P, SENS_18_N, SENS_10_P, SENS_10_N, SENS_120x_P, SENS_120x_N, SENS_120b_P, SENS_120b_N, SENS_VCCA3.3V, SENS_AVCC3.3V, SENS_DVDD1.2V, SENS_+7, SENS_-7_P, SENS_AVTT, SENS_AVCC, SENS_-7_N

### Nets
12VA: FR5.1
AGND: C144.1 C145.2 W2.2
GND: C120.2 C121.1 C124.2 C125.1 C126.2 C127.1 C130.2 C132.1 C138.1 C140.2 C143.2 L6.3 L8.4 R212.1 R217.2 R219.2 U83.25(GND) W2.1
SW+2V: R227.1
SW+4V: R228.1
APWR2.SYNC_DUAL: R219.1 U83.19(SYNC1) ; port APWR2.SYNC_DUAL
PG_SW+2V: U83.10(PG2) ; port PG.PG_SW+2V  [project net PG.PG_SW+2V]
PG_SW+4V: U83.3(PG1) ; port PG.PG_SW+4V  [project net PG.PG_SW+4V]
NetC120_1: C120.1 R206.2
NetC121_2: C121.2 R210.1
NetC124_1: C124.1 C127.2 C143.1 FR5.2 L6.4 L8.3 R216.2 R218.2 TP38.1 U83.2(VIN1) U83.11(VIN2)
NetC125_2: C125.2 C144.2 D5.2(K) R203.1 R227.2 TP35.1
NetC126_1: C126.1 C145.1 D6.2(K) R204.2 R228.2 TP33.1
NetC130_1: C130.1 R206.1 U83.8(VC2)
NetC132_2: C132.2 R210.2 U83.5(VC1)
NetC135_1: C135.1 D5.1(A) L8.2
NetC135_2: C135.2 L8.1 U83.12(SWA2) U83.13(SWB2)
NetC136_1: C136.1 D6.1(A) L6.1
NetC136_2: C136.2 L6.2 U83.1(SWA1) U83.24(SWB1)
NetC138_2: C138.2 U83.20(SS1)
NetC140_1: C140.1 U83.17(SS2)
NetR203_2: R203.2 U83.7(FBX2)
NetR204_1: R204.1 U83.6(FBX1)
NetR212_2: R212.2 U83.21(RT1)
NetR216_1: R216.1 U83.15(~{SHDN2})
NetR217_1: R217.1 U83.16(RT2)
NetR218_1: R218.1 U83.22(~{SHDN1})
NetU83_18: U83.18(SYNC2) U83.23(CLKOUT1)

Not connected (* = marked no-connect by the designer): U83 4(GATE1)* 9(GATE2)* 14(CLKOUT2)*

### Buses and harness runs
harness APWR2 = port APWR2

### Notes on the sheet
- (near L6) DAC Switcher
- Voltage Legend:
  SW+2V = 2V from switcher
  SW+4V = 4V from switcher
  +/- 7V step down from +/- 10V switcher
  DAC Power
  AVCC_3.3V = Power Reference for DAC
  VCCA_3.3V = Digital Power for DAC
  DVDD_1.2V Core = Digital Core for DAC
  Phase Power:
  +7V Power from front end power.
  VREF-PH = 3.0V Reference for Phase Detector
  FPGA Power:
  AVCC1V8 = XADCVCC
  VCC3V3 = VCC
  VCC2V5 = FPGA 2.5V dpwr LVDS Power
  VCC1V8 = VDD = VCCAUX
  VCC1V0 = VCCINT = VCCBRAM
  VREG = 5.1V Linear from FPGA Power
  PCIe
  AVTT = 1.2V
  AVCC = 1.0V
- LT8585EDKD Configs:
  +4V
  RFBX = (Vout-1.204V)/83.3uA
  RFBX = (4.0V-1.204V)/83.3uA
  RFBX = 33.565k => 34.8k
  RT = 76k (1MHz)
  C1 > 1uF
  4uH < Ltyp < 22uH
  COUT >33uF
  +2V
  RFBX = (Vout-1.204V)/83.3uA
  RFBX = (2.0V-1.204V)/83.3uA
  RFBX = 9.55k => 10k
  RT = 76k (1MHz)
  C1 > 1uF
  2.3uH < Ltyp < 12.6uH
  COUT >45uF
- Front End Power +/- 7V
  QC per channel 5.5mA * 64 = 352mA so single supplies are sufficient
  DVDD 1.2V 128 * 4 = 512mA > 500mA so two supplies
  VCCA 3.3V one supply
  AVDD 1.8V one suppply
  AVCC_R 3.3V 90*4 = 360mA one supply
  AVCC_L 3.3V 90*4 = 360mA one supply
  VDD_R, VDD_L 3.3V 128 per DAC * 4 = 512mA > 500mA is two supplies

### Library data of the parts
C120 C121 = ChipCap: C0402 47nF; Part Number: 0402B473J250CT
C124-C127 C143 = ChipCap: C1210 10uF; Part Number: CL32B106KBJNNNE
C130 C132 = ChipCap: C0402 0.1nF; Part Number: 04025A101JAT2A
C135 C136 = ChipCap: as C133 on sheet LD32_Bipolar1
C138 C140 = ChipCap: C0402 0.1uF; Part Number: CL05B104KA5NNNC
C144 C145 = ChipCap: C2220 47uF; Part Number: C5750X7R1E476M230KB
D5 D6 = DIODE_SHOTTKY: Part Number: DFLS230-7
FR5 = BLM31PG121SN1: as FR4 on sheet LD32_Bipolar1
L6 = MSD7342: as L5 on sheet LD32_Bipolar1
L8 = MSD7342: Shielded Coupled Inductors, MSD7342 series 4.7uH; Part Number: MSD7342-472MLC
LOGO?#6 = LIGO_logo
R203 = ChipRes1: R0402 10k; Part Number: ERA-2AEB103X
R204 = ChipRes1: as R241 on sheet LD32_Bipolar1
R206 R210 = ChipRes1: R0402 1.0k; Part Number: ERA-2AEB102X
R212 R217 = ChipRes1: as R211 on sheet LD32_Bipolar1
R216 R218 = ChipRes1: R0402 715k; Part Number: ERA-2AEB7150X
R219 = ChipRes1: R0402 4.7k; Part Number: ERA-2AED472X
R227 R228 = ChipRes1: as R165 on sheet LD32_Bipolar1
TP33 TP35 TP38 = TP_POSITIVE: as TP18 on sheet LD32_Bipolar1
U83 = LT8582: as U82 on sheet LD32_Bipolar1
W2 = NetTie1_small: Tie two nets together; Part Number: NL

## Sheet LD32_PowerFPGA.SchDoc: FPGA Supply
size B; SheetNumber: 5; SheetTotal: 17
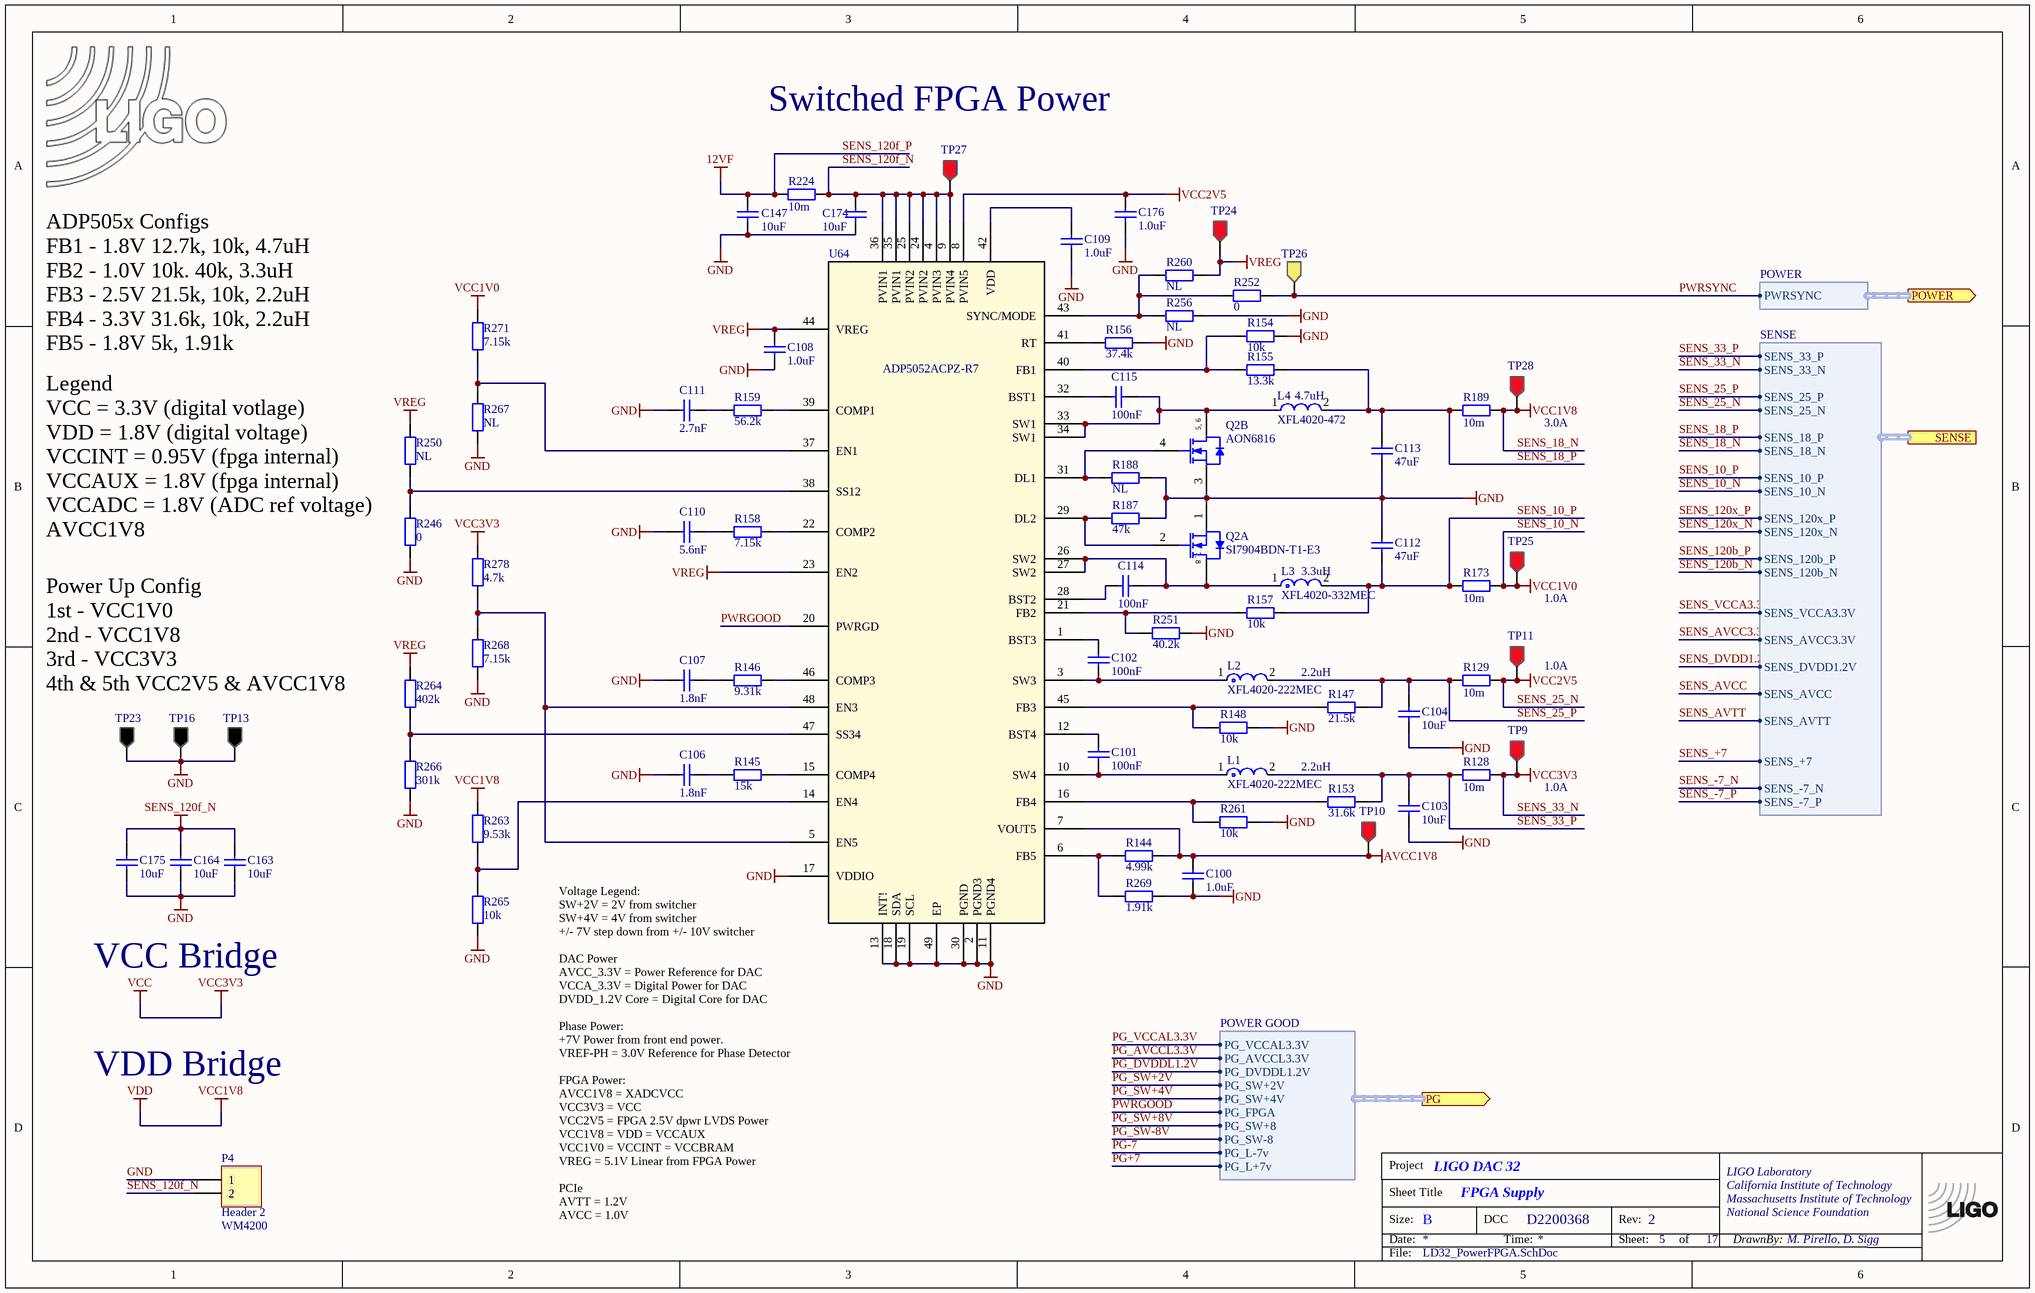
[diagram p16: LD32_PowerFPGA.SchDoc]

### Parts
(Parts that share a designator on the sheet are numbered #1, #2 ... from top to bottom, then left to right.)
*?#13  TitleBlock  (value not drawn)  (graphical)
C100  1.0uF  [CC1005-0402]
C101  100nF  [CC1005-0402]
C102  100nF  [CC1005-0402]
C103  10uF  [CC2013-0805]
C104  10uF  [CC2013-0805]
C106  1.8nF  [CC1005-0402]
C107  1.8nF  [CC1005-0402]
C108  1.0uF  [CC1005-0402]
C109  1.0uF  [CC1005-0402]
C110  5.6nF  [CC1005-0402]
C111  2.7nF  [CC1005-0402]
C112  47uF  [CC3216-1206]
C113  47uF  [CC3216-1206]
C114  100nF  [CC1005-0402]
C115  100nF  [CC1005-0402]
C147  10uF  [CC2013-0805]
C163  10uF  [CC2013-0805]
C164  10uF  [CC2013-0805]
C174  10uF  [CC2013-0805]
C175  10uF  [CC2013-0805]
C176  1.0uF  [CC1005-0402]
L1  XFL4020-222MEC  [FP-XFL4020-MFG]
L2  XFL4020-222MEC  [FP-XFL4020-MFG]
L3  XFL4020-332MEC  [FP-XFL4020-MFG]
L4  XFL4020-472  [FP-XAL40-MFG]
LOGO4#2  LIGO logo  [LIGO_LOGO]  (value not drawn)  (graphical)
P4  Header 2  [WM4200]
Q2  SI7904BDN-T1-E3  [VISH-POWERPAKSO-8_A_V]  (parts A,B of 2)
R128  10m  [CR1608-0603]
R129  10m  [CR1608-0603]
R144  4.99k  [CR1005-0402]
R145  15k  [CR1005-0402]
R146  9.31k  [CR1005-0402]
R147  21.5k  [CR1005-0402]
R148  10k  [CR1005-0402]
R153  31.6k  [CR1005-0402]
R154  10k  [CR1005-0402]
R155  13.3k  [CR1005-0402]
R156  37.4k  [CR1005-0402]
R157  10k  [CR1005-0402]
R158  7.15k  [CR1005-0402]
R159  56.2k  [CR1005-0402]
R173  10m  [CR1608-0603]
R187  47k  [CR1005-0402]
R188  NL  [CR1005-0402]
R189  10m  [CR1608-0603]
R224  10m  [CR1608-0603]
R246  0  [CR1005-0402]
R250  NL  [CR1005-0402]
R251  40.2k  [CR1005-0402]
R252  0  [CR1005-0402]
R256  NL  [CR1005-0402]
R260  NL  [CR1005-0402]
R261  10k  [CR1005-0402]
R263  9.53k  [CR1005-0402]
R264  402k  [CR1005-0402]
R265  10k  [CR1005-0402]
R266  301k  [CR1005-0402]
R267  NL  [CR1005-0402]
R268  7.15k  [CR1005-0402]
R269  1.91k  [CR1005-0402]
R271  7.15k  [CR1005-0402]
R278  4.7k  [CR1005-0402]
TP9  Testpoint  [TP1-RED]  (value not drawn)
TP10  Testpoint  [TP1-RED]  (value not drawn)
TP11  Testpoint  [TP1-RED]  (value not drawn)
TP13  Testpoint  [TP1-BLK]  (value not drawn)
TP16  Testpoint  [TP1-BLK]  (value not drawn)
TP23  Testpoint  [TP1-BLK]  (value not drawn)
TP24  Testpoint  [TP1-RED]  (value not drawn)
TP25  Testpoint  [TP1-RED]  (value not drawn)
TP26  Testpoint  [TP1-YLW]  (value not drawn)
TP27  Testpoint  [TP1-RED]  (value not drawn)
TP28  Testpoint  [TP1-RED]  (value not drawn)
U64  ADP5052ACPZ-R7  [CP-48-13_L]

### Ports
PG (out, harness Power good), POWER (out, harness POWER), SENSE (harness SENSE)

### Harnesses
POWER GOOD: PG_VCCAL3.3V, PG_AVCCL3.3V, PG_DVDDL1.2V, PG_SW+2V, PG_SW+4V, PG_FPGA, PG_SW+8, PG_SW-8, PG_L-7v, PG_L+7v
POWER: PWRSYNC
SENSE: SENS_33_P, SENS_33_N, SENS_25_P, SENS_25_N, SENS_18_P, SENS_18_N, SENS_10_P, SENS_10_N, SENS_120x_P, SENS_120x_N, SENS_120b_P, SENS_120b_N, SENS_VCCA3.3V, SENS_AVCC3.3V, SENS_DVDD1.2V, SENS_+7, SENS_-7_P, SENS_AVTT, SENS_AVCC, SENS_-7_N

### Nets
12VF: C147.1 R224.2  [also labelled SENS_120f_P]
AVCC1V8: C100.2 R144.2 TP10.1 U64.7(VOUT5)
GND: C100.1 C103.1 C104.1 C106.1 C107.1 C108.2 C109.1 C110.1 C111.1 C112.2 C113.1 C147.2 C163.2 C164.2 C174.2 C175.2 C176.1 P4.1 Q2.1(S1) Q2.3(S2) R148.2 R154.2 R156.2 R187.2 R188.2 R246.1 R251.2 R256.2 R261.2 R265.1 R266.1 R267.1 R268.1 R269.2 TP13.1 TP16.1 TP23.1 U64.2(PGND3) U64.11(PGND4) U64.13(INT!) U64.17(VDDIO) U64.18(SDA) U64.19(SCL) U64.30(PGND) U64.49(EP)
SENS_18_N: R189.1 R263.2 TP28.1 ; port SENSE.SENS_18_N  [also labelled VCC1V8, VDD]  [project net VCCAUX]
SENS_120f_N: C163.1 C164.1 C174.1 C175.1 P4.2 R224.1 TP27.1 U64.4(PVIN3) U64.9(PVIN4) U64.24(PVIN2) U64.25(PVIN2) U64.35(PVIN1) U64.36(PVIN1)
VCC: R128.1 R278.2 TP9.1 ; port SENSE.SENS_33_N  [also labelled SENS_33_N, VCC3V3]
VCC1V0: R173.1 R271.2 TP25.1 ; port SENSE.SENS_10_N  [also labelled SENS_10_N]
VCC2V5: C176.2 R129.1 TP11.1 U64.8(PVIN5) ; port SENSE.SENS_25_N  [also labelled SENS_25_N]
VREG: C108.1 R250.2 R260.2 R264.2 TP24.1 U64.23(EN2) U64.44(VREG)
PWRGOOD: U64.20(PWRGD) ; port PG.PG_FPGA  [project net PG.PG_FPGA]
PWRSYNC: R252.2 TP26.1 ; port POWER.PWRSYNC  [project net POWER.PWRSYNC]
SENS_10_P: C112.1 L3.2 R157.2 R173.2 ; port SENSE.SENS_10_P  [project net SENSE.SENS_10_P]
SENS_18_P: C113.2 L4.2 R155.2 R189.2 ; port SENSE.SENS_18_P  [project net SENSE.SENS_18_P]
SENS_25_P: C104.2 L2.2 R129.2 R147.2 ; port SENSE.SENS_25_P  [project net SENSE.SENS_25_P]
SENS_33_P: C103.2 L1.2 R128.2 R153.2 ; port SENSE.SENS_33_P  [project net SENSE.SENS_33_P]
NetC101_1: C101.1 L1.1 U64.10(SW4)
NetC101_2: C101.2 U64.12(BST4)
NetC102_1: C102.1 L2.1 U64.3(SW3)
NetC102_2: C102.2 U64.1(BST3)
NetC106_2: C106.2 R145.1
NetC107_2: C107.2 R146.1
NetC109_2: C109.2 U64.42(VDD)
NetC110_2: C110.2 R158.1
NetC111_2: C111.2 R159.1
NetC114_1: C114.1 U64.28(BST2)
NetC114_2: C114.2 L3.1 Q2.7(D1) Q2.8(D1) U64.26(SW2) U64.27(SW2)
NetC115_1: C115.1 U64.32(BST1)
NetC115_2: C115.2 L4.1 Q2.5(D2) Q2.6(D2) U64.33(SW1) U64.34(SW1)
NetQ2_2: Q2.2(G1) R187.1 U64.29(DL2)
NetQ2_4: Q2.4(G2) R188.1 U64.31(DL1)
NetR144_1: R144.1 R269.1 U64.6(FB5)
NetR145_2: R145.2 U64.15(COMP4)
NetR146_2: R146.2 U64.46(COMP3)
NetR147_1: R147.1 R148.1 U64.45(FB3)
NetR153_1: R153.1 R261.1 U64.16(FB4)
NetR154_1: R154.1 R155.1 U64.40(FB1)
NetR156_1: R156.1 U64.41(RT)
NetR157_1: R157.1 R251.1 U64.21(FB2)
NetR158_2: R158.2 U64.22(COMP2)
NetR159_2: R159.2 U64.39(COMP1)
NetR246_2: R246.2 R250.1 U64.38(SS12)
NetR252_1: R252.1 R256.1 R260.1 U64.43(SYNC/MODE)
NetR263_1: R263.1 R265.2 U64.14(EN4)
NetR264_1: R264.1 R266.2 U64.47(SS34)
NetR267_2: R267.2 R271.1 U64.37(EN1)
NetR268_2: R268.2 R278.1 U64.5(EN5) U64.48(EN3)

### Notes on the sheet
- Switched FPGA Power
- ADP505x Configs
  FB1 - 1.8V 12.7k, 10k, 4.7uH
  FB2 - 1.0V 10k. 40k, 3.3uH
  FB3 - 2.5V 21.5k, 10k, 2.2uH
  FB4 - 3.3V 31.6k, 10k, 2.2uH
  FB5 - 1.8V 5k, 1.91k
- (near L4) 4.7uH
- 3.0A
- Legend
  VCC = 3.3V (digital votlage)
  VDD = 1.8V (digital voltage)
  VCCINT = 0.95V (fpga internal)
  VCCAUX = 1.8V (fpga internal)
  VCCADC = 1.8V (ADC ref voltage)
  AVCC1V8
- (near L3) 3.3uH
- 1.0A
- 2.2uH
- (near TP11) 1.0A
- Power Up Config
  1st - VCC1V0
  2nd - VCC1V8
  3rd - VCC3V3
  4th & 5th VCC2V5 & AVCC1V8
- VCC Bridge
- VDD Bridge
- (near U64) Voltage Legend:
  SW+2V = 2V from switcher
  SW+4V = 4V from switcher
  +/- 7V step down from +/- 10V switcher
  DAC Power
  AVCC_3.3V = Power Reference for DAC
  VCCA_3.3V = Digital Power for DAC
  DVDD_1.2V Core = Digital Core for DAC
  Phase Power:
  +7V Power from front end power.
  VREF-PH = 3.0V Reference for Phase Detector
  FPGA Power:
  AVCC1V8 = XADCVCC
  VCC3V3 = VCC
  VCC2V5 = FPGA 2.5V dpwr LVDS Power
  VCC1V8 = VDD = VCCAUX
  VCC1V0 = VCCINT = VCCBRAM
  VREG = 5.1V Linear from FPGA Power
  PCIe
  AVTT = 1.2V
  AVCC = 1.0V

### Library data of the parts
C100 C108 C109 C176 = ChipCap: as C137 on sheet LD32_Bipolar1
C101 C102 C114 C115 = ChipCap: as C138 on sheet LD32_Bipolar2
C103 C104 C147 C163 C164 C174 C175 = ChipCap: C0805 10uF; Part Number: CL21A106KAYNNNG
C106 C107 = ChipCap: C0402 1.8nF; Part Number: C0402C182J3GACTU
C110 = ChipCap: C0402 5.6nF; Part Number: CL05B562KA5NNNC
C111 = ChipCap: C0402 2.7nF; Part Number: C0402C272K3RAC7867
C112 C113 = ChipCap: C1206 47uF; Part Number: C3216X5R1E476M160DC
L1 L2 = CMP-2000-05090-4: INDUCTOR, 2.2UH, 8A, 20%, 38MHZ, REEL
L3 = CMP-11268-000187-1: Fixed Inductors 3.3Uh Shld 5.2A 38.3mOhms AECQ2
L4 = CMP-11268-000008-1: INDUCTOR, 4.7uH; Part Number: XFL4020-472MEC
LOGO4#2 = LIGO_logo
P4 = WM4200: Header, 2-Pin
Q2 = CMP-2000-07602-1: Dual N-Channel (D-S) MOSFET, 100 V, 36.7 A, -55 to 150 degC, 8-Pin SMD, RoHS, Tape and Reel; Part Number: AON6816
R128 R129 R173 R189 R224 = ChipRes1: as R165 on sheet LD32_Bipolar1
R144 = ChipRes1: R0402 4.99k; Part Number: RR0510P-4991-D
R145 = ChipRes1: R0402 15k; Part Number: ERA-2AEB153X
R146 = ChipRes1: R0402 9.31k; Part Number: 311-2336-1-ND
R147 = ChipRes1: R0402 21.5k; Part Number: RR0510P-2152-D
R148 R154 R157 R261 R265 = ChipRes1: R0402 10k; Part Number: ERA-2AEB103X
R153 = ChipRes1: R0402 31.6k; Part Number: RT0402DRE0731K6L
R155 = ChipRes1: R0402 13.3k; Part Number: ERA-2AEB1332X
R156 = ChipRes1: R0402 37.4k; Part Number: CR0402-FX-3742GLF
R158 R268 R271 = ChipRes1: R0402 7.15k; Part Number: RT0402BRD077K15L
R159 = ChipRes1: R0402 56.2k; Part Number: 311-2303-1-ND
R187 = ChipRes1: R0402 47k; Part Number: RG10P47KBCT-ND
R188 R250 R256 R260 R267 = ChipRes1
R246 R252 = ChipRes1: R0402 0; Part Number: AC0402FR-070RL
R251 = ChipRes1: R0402 40.2k; Part Number: ERA-2ARC4022X
R263 = ChipRes1: R0402 9.53k; Part Number: RT0402BRD079K53L
R264 = ChipRes1: R0402 402k; Part Number: RMCF0402FT402KCT-ND
R266 = ChipRes1: R0402 301k; Part Number: RMCF0402FT301KCT-ND
R269 = ChipRes1: R0402 1.91k; Part Number: RT0402BRD071K91L
R278 = ChipRes1: R0402 4.7k; Part Number: ERA-2AED472X
TP9-TP11 TP24 TP25 TP27 TP28 = TP_POSITIVE: as TP18 on sheet LD32_Bipolar1
TP13 TP16 TP23 = TP_GND: as TP32 on sheet LD32_Bipolar1
TP26 = TP_SIGNAL: Testpoint, yellow; Part Number: Keystone / 5004
U64 = ADP5050ACPZ-R7: Artix 7 Power Supply; Part Number: ADP5050ACPZ-R7CT-ND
